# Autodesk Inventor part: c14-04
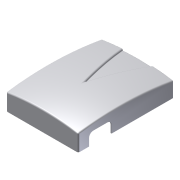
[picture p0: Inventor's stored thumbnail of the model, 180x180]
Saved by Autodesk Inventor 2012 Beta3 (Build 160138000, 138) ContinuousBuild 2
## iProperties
Created: 2011-01
Part Number: c14-04
Material: Default
Document SubType Name: Modeling
Designer: Beta-8540w
Density: 1 g/cm^3
Author: Beta-8540w
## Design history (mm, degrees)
sketch "Sketch1"
  geometry: L1 (-75, 100)-(75, 100); L2 (75, 100)-(75, -100); L3 (75, -100)-(-75, -100); L4 (-75, -100)-(-75, 100); 3 further points
  constraints: 8 end point, 2 midpoint, 2 parallel, 1 horizontal, 1 horizontal alignment, 1 perpendicular, 1 vertical alignment
  dimensions: "d0" = 150 distance of L2.end L3.end; "d1" = 200 distance of L1.end L2.end
extrude "Extrusion1" new body sketch "Sketch1" distance "d2" = 40; taper "d3" = 0 deg
sketch "Sketch2"
  geometry: L1 (150, 40)-(0, 40) reference; L2 (0, 0)-(0, 40) reference; L3 (150, 0)-(150, 40) reference; L4 (0, 34)-(150, 34); A1 r 471.75 centre (75, -431.75) between (150, 34) and (0, 34); 1 further point
  constraints: 2 end point, 2 point on circle, 2 point on line, 1 centre point, 1 perpendicular, 1 tangent
  dimensions: "d4" = 6 distance between parallel lines of L1 L4
sketch "Sketch3"
  geometry: L1 (-40, 200)-(-40, 0) reference; L2 (0, 200)-(-40, 200) reference; A1 r 639.211 centre (599.211, 87.376) between (-30, 200) and (-34, 0); 1 further point
  constraints: 2 point on circle, 1 centre point, 1 point on line, 1 tangent
  dimensions: "d5" = 10 distance of L1.start A1.start
feature "SweepSrf1" sketch "Sketch2", "Sketch3" dims "d6" = 0
feature "Replace Face1"
feature "OffsetSrf1" dims "d7" = 3, "d8" = 3
sketch "Sketch4"
  geometry: L1 (75, 100)-(-75, 100) reference; L2 (75, -100)-(75, 100) reference; L3 (-33.106, 112.861)-(0, -3.125); L4 (0, -3.125)-(33.106, 112.861); L5 (33.106, 112.861)-(-33.106, 112.861); 4 further points
  constraints: 6 end point, 3 midpoint, 2 vertical alignment, 1 perpendicular
extrude_surface "ExtrusionSrf1" sketch "Sketch4" dims "d9" = 60.5, "d10" = 5 deg
feature "Extend1" dims "d11" = 12.5
feature "Sculpt1"
fillet "Fillet1" dims "d12" = 1.5, "d13" = 1
shell "Shell1" dims "d14" = 2
sketch "Sketch5"
  geometry: L1 (0, 0)-(0, 198) reference; L2 (12.476, 163)-(0, 163); L3 (12.476, 175)-(0, 175); L4 (0, 163)-(0, 175); C1 r 5 at (12.476, 169) reference; A1 r 6 centre (12.476, 169) between (12.476, 163) and (12.476, 175); 1 further point
  constraints: 6 end point, 2 point on circle, 2 point on line, 2 tangent, 1 centre point, 1 collinear, 1 parallel, 1 perpendicular
  dimensions: "d15" = 1 radial gap between concentric circles of A1 C1
extrude "Extrusion2" cut sketch "Sketch5" stored distance "d16" = 60.5; taper "d17" = 0 deg
sketch "Sketch6"
  geometry: L1 (0, 198)-(0, 0) reference; L2 (0, 20)-(-16, 20); L3 (-25, 29)-(-25, 59); L4 (-16, 68)-(0, 68); L5 (0, 20)-(0, 68); C1 r 6.858 at (-16, 59) reference; C2 r 7 at (-16, 29) reference; A1 r 9 centre (-16, 29) between (-25, 29) and (-16, 20); A2 r 9 centre (-16, 59) between (-16, 68) and (-25, 59); 1 further point
  constraints: 8 end point, 4 perpendicular, 4 point on circle, 4 tangent, 2 centre point, 2 coincident, 2 point on line
  dimensions: "d18" = 9 radius of A1
extrude "Extrusion3" cut sketch "Sketch6" stored distance "d19" = 60.5; taper "d20" = 0 deg
sketch "Sketch7" dims "d30" = 10, "d38" = 10
  geometry: L1 (0, 0)-(148, 0) reference; L2 (14, -4)-(134, -4); L3 (134, -4)-(134, -20); L4 (134, -20)-(14, -20); L5 (14, -20)-(14, -4); L6 (14, -9.333)-(134, -9.333); L7 (38, -4)-(38, -20); L8 (14, -14.667)-(134, -14.667); L9 (62, -4)-(62, -20); L10 (86, -4)-(86, -20); L11 (110, -4)-(110, -20); 3 further points
  constraints: 20 end point, 4 point on line, 3 perpendicular, 2 horizontal, 2 midpoint, 2 parallel, 1 vertical, 1 vertical alignment, 12 other
  dimensions: "d21" = 120 distance of L2.start L2.end; "d22" = 16 distance of L4.end L2.start; "d23" = 4 distance of point (74, 0) point (74, -4); "d24" = 5.33333 distance between parallel lines of L2 L6 (= 0.333333 x d22); "d27" = 5.33333 distance of L6.start L8.start (= d24); "d32" = 24 distance between parallel lines of L7 L5 (= 0.2 x d21); "d35" = 24 distance of L7.start L9.start (= d32)
feature "Grill1" sketch "Sketch7" dims "d41" = 2, "d42" = 0, "d43" = 0, "d44" = 2, "d45" = 0, "d46" = 2, "d47" = 0, "d48" = 0, "d49" = 1, "d50" = 0, "d51" = 0, "d52" = 0, "d53" = 134.4
fillet "Fillet2" dims "d54" = 1
fillet "Fillet3" dims "d55" = 1
body "Solid1"
body "Srf1"
body "Srf2"
body "Srf3"
node "Reference1"
node "Reference2"
node "Reference3"
other parameters: "d40" = 2
